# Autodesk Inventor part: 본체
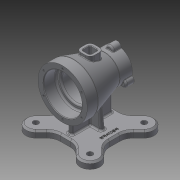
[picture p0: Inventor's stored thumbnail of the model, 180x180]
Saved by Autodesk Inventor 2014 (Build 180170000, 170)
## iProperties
Created: 2018-03
Part Number: 본체
Material: 일반
Document SubType Name: Modeling
Designer: 601-10
Density: 1 g/cm^3
Appearance: 기본값
Mass: 366.095 g
Surface Area: 851.87 cm^2
Volume: 366.095 cm^3
Author: 601-10
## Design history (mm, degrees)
sketch "스케치1"
  geometry: L1 (0, 50)-(0, -50); L2 (0, 50)-(45, 50); L3 (45, 50)-(45, 30); L4 (45, 30)-(27.5, -27); L5 (27.5, -27)-(27.5, -50); L6 (27.5, -50)-(0, -50); L7 (35, 50)-(35, 30); L8 (32, 27)-(29, 27); L9 (26, 24)-(26, -17); L10 (23, -20)-(23, -20); L11 (20, -23)-(20, -50); A1 r 3 centre (32, 30) between (32, 27) and (35, 30); A2 r 3 centre (29, 24) between (29, 27) and (26, 24); A3 r 3 centre (23, -17) between (23, -20) and (26, -17); A4 r 3 centre (23, -23) between (23, -20) and (20, -23); 6 further points
  constraints: 22 end point, 10 point on line, 8 point on circle, 8 tangent, 6 perpendicular, 4 centre point, 3 equal radius, 3 parallel, 1 coincident, 1 midpoint, 1 vertical
  dimensions: "d0" = 100 distance of L1.start L1.end; "d1" = 90 diameter of L3 L1; "d3" = 55 diameter of L5 L1; "d4" = 20 distance of L2.end L3.end; "d5" = 77 distance from line of L2 L4.end; "d6" = 70 diameter of L7 L1; "d7" = 23 distance between parallel lines of L2 L8; "d8" = 52 diameter of L9 L1; "d9" = 47 distance between parallel lines of L8 L10; "d10" = 40 diameter of L11 L1; "d11" = 30 distance between parallel lines of L6 L10 (derived); "d38" = 3 radius of A1
revolve "회전1" sketch "스케치1" stored, may be unused: angle "d12" = 90 deg
node "작업 평면1"
sketch "스케치2"
  geometry: L1 (-9.189, 45)-(9.189, 45); L2 (45, 9.189)-(45, -9.189); L3 (9.189, -45)-(-9.189, -45); L4 (-45, -9.189)-(-45, 9.189); L5 (-45, 45)-(45, -45); L6 (45, 45)-(-45, -45); L7 (-45, 50)-(45, 50) reference; L8 (49.497, 49.497)-(25.887, 25.887); L9 (36.77, 62.225)-(26.866, 52.322); L10 (52.322, 26.866)-(62.225, 36.77); L11 (0, 70)-(0, -70); L12 (-26.866, 52.322)-(-36.77, 62.225); L13 (-62.225, 36.77)-(-52.322, 26.866); L14 (-52.322, -26.866)-(-62.225, -36.77); L15 (-36.77, -62.225)-(-26.866, -52.322); L16 (26.866, -52.322)-(36.77, -62.225); L17 (62.225, -36.77)-(52.322, -26.866); L18 (-1, 37)-(1, 37); L19 (4, 34)-(4, -34); L20 (1, -37)-(-1, -37); L21 (-4, -34)-(-4, 34); L22 (-4, 37)-(4, -37); L23 (4, 37)-(-4, -37); C1 r 5 at (49.497, -49.497); C2 r 5 at (49.497, 49.497); C3 r 5 at (-49.497, 49.497); C4 r 5 at (-49.497, -49.497); A1 r 18 centre (49.497, 49.497) between (62.225, 36.77) and (36.77, 62.225); A2 r 18 centre (25.887, 25.887) between (13.159, 38.615) and (38.615, 13.159); A3 r 70 centre (0, 0) between (49.497, 49.497) and (0, 70); A4 r 18 centre (-49.497, 49.497) between (-36.77, 62.225) and (-62.225, 36.77); A5 r 18 centre (-49.497, -49.497) between (-62.225, -36.77) and (-36.77, -62.225); A6 r 18 centre (49.497, -49.497) between (36.77, -62.225) and (62.225, -36.77); A7 r 25 centre (70, 9.189) between (52.322, 26.866) and (45, 9.189); A8 r 25 centre (70, -9.189) between (45, -9.189) and (52.322, -26.866); A9 r 25 centre (9.189, -70) between (26.866, -52.322) and (9.189, -45); A10 r 25 centre (-9.189, -70) between (-9.189, -45) and (-26.866, -52.322); A11 r 25 centre (-70, -9.189) between (-52.322, -26.866) and (-45, -9.189); A12 r 25 centre (-70, 9.189) between (-45, 9.189) and (-52.322, 26.866); A13 r 25 centre (-9.189, 70) between (-26.866, 52.322) and (-9.189, 45); A14 r 25 centre (9.189, 70) between (9.189, 45) and (26.866, 52.322); A15 r 3 centre (1, 34) between (4, 34) and (1, 37); A16 r 3 centre (-1, 34) between (-1, 37) and (-4, 34); A17 r 3 centre (-1, -34) between (-4, -34) and (-1, -37); A18 r 3 centre (1, -34) between (1, -37) and (4, -34); 10 further points
  constraints: 46 end point, 37 point on circle, 28 tangent, 25 point on line, 22 centre point, 9 equal radius, 6 midpoint, 5 parallel, 3 coincident, 3 perpendicular, 2 horizontal, 42 other
  dimensions: "d14" = 90 distance of L5.end L6.end; "d15" = 90 distance of L6.start L5.end; "d16" = 50 distance from line of L7 point (0, 0); "d17" = 36 diameter of A2; "d18" = 140 diameter of A3; "d19" = 45 deg angle of L11 L8; "d22" = 360 deg dimension on A3.centre L8.start (derived); "d24" = 25 radius of A7; "d25" = 25 radius of A11; "d26" = 10 diameter of C1; "d29" = 360 deg dimension on A3.centre C1.centre (derived); "d31" = 8 distance of L22.end L23.end; "d32" = 74 distance of L23.start L22.end; "d33" = 3 radius of A15
extrude "돌출1" join sketch "스케치2" distance "d34" = 12; taper "d35" = 0 deg
extrude "돌출2" join sketch "스케치2" stored distance "d36" = 0; taper "d37" = 0 deg
sketch "스케치3"
  geometry: L1 (36.77, -70)-(26.866, -70) reference; L2 (-26.866, -70)-(-36.77, -70) reference; L3 (24, -70)-(19.844, -22.499); L4 (-19.844, -22.499)-(-24, -70); L5 (-24, -70)-(24, -70); A1 r 30 centre (0, 0) between (-19.844, -22.499) and (19.844, -22.499); 1 further point
  constraints: 6 end point, 2 point on circle, 2 point on line, 1 centre point, 1 coincident, 1 collinear
  dimensions: "d39" = 24 horizontal distance of point (0, 0) L3.start; "d40" = 95 deg angle of L1 L3; "d41" = 24 horizontal distance of point (0, 0) L4.end; "d42" = 95 deg angle of L2 L4; "d43" = 60 diameter of A1
extrude "돌출3" join sketch "스케치3" stored distance "d44" = 8; taper "d45" = 0 deg
sketch "스케치4"
  geometry: C1 r 7 at (0, 27.5); C2 r 7 at (-23.816, -13.75); C3 r 7 at (23.816, -13.75); 1 further point
  constraints: 3 centre point, 2 vertical alignment, 8 other
  dimensions: "d47" = 14 diameter of C1; "d50" = 360 deg dimension on point (0, 0) C1.centre (derived)
extrude "돌출4" join sketch "스케치4" distance "d52" = 15; taper "d53" = 0 deg
sketch "스케치5"
  geometry: A1 r 7 centre (0, 0) between (6.943, -0.891) and (-6.943, -0.891) reference; A2 r 7 centre (-23.816, -41.25) between (-26.516, -34.792) and (-19.573, -46.817) reference; A3 r 7 centre (23.816, -41.25) between (19.573, -46.817) and (26.516, -34.792) reference; 3 further points
  constraints: 3 coincident
hole "구멍1" sketch "스케치5" at (0, 0), (23.816, -41.25), (-23.816, -41.25) diameter "d54" = 3.242; stored, may be unused: countersink angle "d58" = 90 deg, drill point angle "d60" = 118 deg; dims "d55" = 9, "d56" = 4, "d57" = 2, "d59" = 11
node "작업 평면2"
sketch "스케치6"
  geometry: L1 (4.5, 12.5)-(-4.5, 12.5); L2 (-12.5, 4.5)-(-12.5, -4.5); L3 (-4.5, -12.5)-(4.5, -12.5); L4 (12.5, -4.5)-(12.5, 4.5); L5 (12.5, 12.5)-(-12.5, -12.5); L6 (-12.5, 12.5)-(12.5, -12.5); L7 (-4.5, 7.5)-(4.5, 7.5); L8 (7.5, 4.5)-(7.5, -4.5); L9 (4.5, -7.5)-(-4.5, -7.5); L10 (-7.5, -4.5)-(-7.5, 4.5); L11 (-7.5, 7.5)-(7.5, -7.5); L12 (7.5, 7.5)-(-7.5, -7.5); A1 r 8 centre (4.5, 4.5) between (12.5, 4.5) and (4.5, 12.5); A2 r 8 centre (4.5, -4.5) between (4.5, -12.5) and (12.5, -4.5); A3 r 8 centre (-4.5, -4.5) between (-12.5, -4.5) and (-4.5, -12.5); A4 r 8 centre (-4.5, 4.5) between (-4.5, 12.5) and (-12.5, 4.5); A5 r 3 centre (4.5, 4.5) between (7.5, 4.5) and (4.5, 7.5); A6 r 3 centre (-4.5, 4.5) between (-4.5, 7.5) and (-7.5, 4.5); A7 r 3 centre (-4.5, -4.5) between (-7.5, -4.5) and (-4.5, -7.5); A8 r 3 centre (4.5, -4.5) between (4.5, -7.5) and (7.5, -4.5); 1 further point
  constraints: 24 end point, 16 point on circle, 16 point on line, 16 tangent, 8 centre point, 6 equal radius, 4 midpoint, 4 parallel, 2 horizontal, 2 perpendicular
  dimensions: "d62" = 25 distance of L6.end L5.end; "d63" = 25 distance of L5.end L6.start; "d64" = 15 distance of L11.end L12.end; "d65" = 15 distance of L12.start L11.end; "d66" = 8 radius of A1; "d67" = 3 radius of A5
extrude "돌출5" join sketch "스케치6" stored distance "d68" = 15; taper "d69" = 0 deg
extrude "돌출6" cut sketch "스케치6" stored distance "d70" = 15; taper "d71" = 0 deg
sketch "스케치7" dims "d72" = 80
  geometry: C1 r 35 at (0, 0) reference; C2 r 45 at (0, 0) reference; 2 further points
  constraints: 2 vertical alignment, 1 coincident, 2 other
hole "구멍2" sketch "스케치7" at (0, 40) diameter "d73" = 3.242; stored, may be unused: countersink angle "d77" = 90 deg, drill point angle "d79" = 118 deg; dims "d74" = 9, "d75" = 4, "d76" = 2, "d78" = 11
chamfer "모따기1" distance "d83" = 1; stored, may be unused: second distance "d84" = 2, angle "d85" = 45 deg
chamfer "모따기2" distance "d86" = 3; stored, may be unused: second distance "d87" = 2, angle "d88" = 45 deg
fillet "모깎기2" dims "d90" = 3
fillet "모깎기3" dims "d91" = 1
node "작업 평면3"
sketch "스케치9"
  geometry: L1 (9.189, 45)-(-9.189, 45) reference; 2 further points
  constraints: 1 other
  dimensions: "d95" = 35 distance of point (0, 0) point (35, 0); "d96" = 45 distance from line of L1 point (35, 0)
feature "엠보싱1" sketch "스케치9" dims "d8" = 52, "d97" = 0.5, "d98" = 0
node "솔리드1"
pattern_circular "원형 패턴1" dims angle "d81" = 360 deg
other parameters: "d13" = -82, "d61" = 45, "d94" = 5
